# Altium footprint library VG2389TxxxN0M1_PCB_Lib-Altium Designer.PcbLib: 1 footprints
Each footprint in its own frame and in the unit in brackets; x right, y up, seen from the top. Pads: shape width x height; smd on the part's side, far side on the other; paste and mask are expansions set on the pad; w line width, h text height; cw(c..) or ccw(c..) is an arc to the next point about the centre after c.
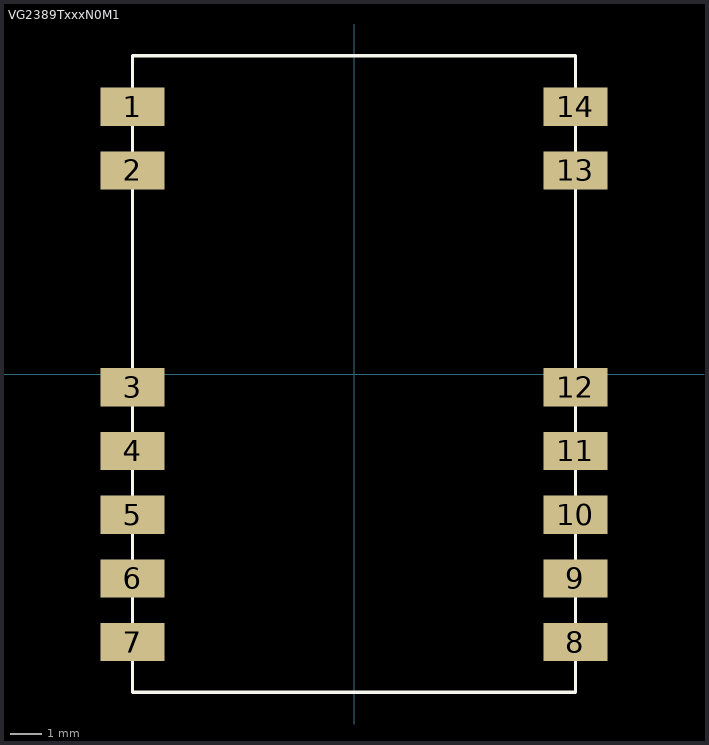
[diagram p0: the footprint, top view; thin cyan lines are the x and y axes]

## VG2389TxxxN0M1 [mm]
pads (14):
  rrect0% 2x1.2 smd: 1(-6.95,8.4) 2(-6.95,6.4) 3(-6.95,-0.4) 4(-6.95,-2.4) 5(-6.95,-4.4) 6(-6.95,-6.4) 7(-6.95,-8.4) 8(6.95,-8.4) 9(6.95,-6.4) 10(6.95,-4.4) 11(6.95,-2.4) 12(6.95,-0.4) 13(6.95,6.4) 14(6.95,8.4)
Top Overlay:
  lines w0.1: -6.95,-9.971 6.95,-9.971 6.95,9.997 -6.95,9.997 -6.95,-9.971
